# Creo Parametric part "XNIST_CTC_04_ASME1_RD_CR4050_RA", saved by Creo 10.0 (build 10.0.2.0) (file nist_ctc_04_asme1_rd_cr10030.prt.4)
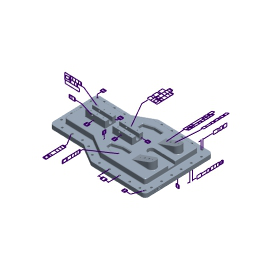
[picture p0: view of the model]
Units: millimeter Kilogram Sec (mmKs); MM, KILOGRAM, SECS

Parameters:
  PART_NUMBER = "NIST PMI CTC 04 ASME1"
  REVISION = "D"
  DESCRIPTION = "NIST PMI test model downloaded from http://go.usa.gov/mGVm"
  PTC_MASTER_MATERIAL = "PTC_SYSTEM_MTRL_PROPS"
  METRIC = "YES"
  SCREW_SIZE = "M12x1.75"

Other parameters: PITCH, DRILL_POINT_ANGLE, DRILL_DEPTH, DRILL_DIAMETER, THREAD_DIAMETER, THREADS_PER_INCH, THREAD_DEPTH, THREAD_LENGTH

Created from: NIST_CTC_04_ASME1_RD_CR4050_RA.PRT

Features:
  1. datum plane "RIGHT"
  2. datum plane "TOP"
  3. datum plane "FRONT"
  4. coordinate system
  5. curve
  6. protrusion
  7. curve
  8. pattern
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
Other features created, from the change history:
  feature "Divide Surface 1"

Other named items: PROFILE-REGION, CS0, DRF_ABC, DRF_DGH, DRF_D, DRF_DEF, DRF_DE, AD1062, AD1070, AD1072, AD1074, GP8, AD1078, AD1079, AD1081, AD1082, AD1083, AD1084, GP13, GP14, GP15, GP16, DATUM_TAG_A, DATUM_TAG_B, DATUM_TAG_C, DATUM_TAG_D, DATUM_TAG_E, DATUM_TAG_F, DATUM_TAG_G, DATUM_TAG_H, MBD_0, ANNOT_LAYER_STATE0018

Notes:  j|n 0.35 | A | B | C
